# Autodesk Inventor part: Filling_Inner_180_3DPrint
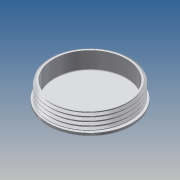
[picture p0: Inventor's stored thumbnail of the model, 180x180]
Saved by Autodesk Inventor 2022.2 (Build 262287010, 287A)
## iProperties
Created: 2022-03
Part Number: Filling_Inner_180_3DPrint
Material: Aluminum 6061
Document SubType Name: Modeling
Designer: dotwibo2
Density: 2.71 g/cm^3
Appearance: Aluminum - Flat
Author: dotwibo2
Created: 2021-11
Part Number: inner_filling
Material: PLA filament White
Density: 1.384 g/cm^3
Appearance: White PLA
Mass: 214.853 g
Surface Area: 857.916 cm^2
Volume: 155.241 cm^3
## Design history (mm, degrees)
sketch "Sketch2"
  geometry: L1 (-7.4, 0)-(44.4, 0) reference; L2 (0, -16.6)-(0, 99.6) reference; L3 (3, 0)-(3, 72); L4 (0, 0)-(0, 83); L5 (0, 83)-(5, 83); L6 (5, 83)-(5, 75.375); L7 (3, 72)-(37, 72); L8 (37, 72)-(37, 75.375); L9 (37, 75.375)-(5, 75.375); 2 further points
  constraints: 14 end point, 4 vertical, 3 horizontal, 2 point on line, 1 collinear, 1 horizontal alignment
  dimensions: "d2" = 3 distance between parallel lines of L3 L2; "d3" = 37 distance between parallel lines of L2 L8; "d4" = 5 distance between parallel lines of L2 L6; "d5" = 144 diameter of L7 L1; "d6" = 166 diameter of L5 L1; "d54" = 150.75 diameter of L9 L1
revolve "Revolution1" sketch "Sketch2" stored, may be unused: angle "d9" = 90 deg
fillet "Fillet1" dims "d57" = 2
sketch "Sketch4"
  geometry: L1 (6, 82.039)-(2, 75.111); L2 (2, 75.111)-(-2, 82.039); L3 (-2, 82.039)-(-6, 75.111); L4 (-25.047, 0)-(76.328, 0) reference; L5 (0, -108.448)-(0, 125.298) reference; L6 (-6, 75.111)-(-10.082, 82.181); L7 (38.002, 75.111)-(19.603, 75.111); L8 (-2, 82.039)-(6, 82.039); L9 (61.846, -75.111)-(15.468, -75.111); L10 (2.499, 75.975)-(1.501, 75.975); L11 (2, 73.711)-(-1.501, 79.775); L12 (-2, 80.639)-(-2.499, 79.775); L13 (-6, 73.711)-(2, 73.711); L14 (-1.501, 79.775)-(-2.499, 79.775); L15 (2, 74.411)-(-2, 81.339); L16 (-2, 81.339)-(-6, 74.411); L17 (2, 74.411)-(11.616, 91.066); L18 (2, 73.711)-(12.504, 91.905); L19 (-6, 74.411)-(-0.583, 65.028); L20 (-6, 73.711)-(-8.164, 77.458); L21 (41.021, 77.875)-(-2.64, 77.875); L22 (44.753, 80.375)-(-10.082, 80.375); L23 (44.733, 75.375)-(-10.565, 75.375); L24 (-1.501, 79.775)-(-2, 80.639); L25 (-2.499, 79.775)-(-6, 73.711); 2 further points
  constraints: 46 end point, 13 parallel, 9 horizontal, 5 point on line, 1 midpoint, 1 vertical alignment, 5 other
  dimensions: "d10" = 30 deg angle of L5 L1; "d11" = 30 deg angle of L5 L2; "d12" = 2 distance from line of L5 L1.end; "d13" = 150.2218 diameter of L1.end L4 (derived); "d14" = 8 distance of L1.end L3.end; "d15" = 0.99778 distance of L10.start L10.end (derived); "d23" = 151.95 diameter of L10 L4 (derived); "d24" = 0.99778 distance of L11.end L12.end (derived); "d25" = 159.55 diameter of L14 L4 (derived); "d27" = 0.7 distance between parallel lines of L11 L2; "d29" = 155.75 diameter of L21 L4; "d58" = 160.75 diameter of L22 L4; "d59" = 0.6 distance between parallel lines of L14 L22; "d60" = 150.75 diameter of L23 L4 (= d54); "d61" = 0.6 distance between parallel lines of L23 L10
coil "Coil1" sketch "Sketch4" pitch "d30" = 8; turns "d32" = 1; dims "d31" = 45, "d33" = 0, angle "d34" = 90 deg, angle "d35" = 90 deg, "d36" = 0, "d37" = 0
sketch "Sketch5"
  geometry: L1 (5, 85)-(31.443, 85); L2 (31.443, 85)-(37, 75.375); L3 (37, 75.375)-(5, 75.375); L4 (5, 75.375)-(5, 85); L5 (-7.4, 0)-(44.4, 0) reference; L6 (0, -17)-(0, 102) reference; 1 further point
  constraints: 8 end point, 1 horizontal, 1 parallel, 1 vertical
  dimensions: "d40" = 150.75 diameter of L3 L5 (= d54); "d45" = 170 diameter of L1 L5; "d46" = 37 distance from line of L6 L2.end (= d3); "d47" = 5 distance from line of L6 L3.end (= d4); "d55" = 60 deg angle of L3 L2
revolve "Revolution2" sketch "Sketch5" stored, may be unused: angle "d41" = 90 deg
combine "Combine1"
  body "Solid4"
node "NEW_FILLING"
body "Solid1"
